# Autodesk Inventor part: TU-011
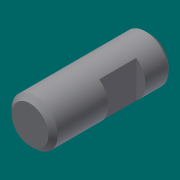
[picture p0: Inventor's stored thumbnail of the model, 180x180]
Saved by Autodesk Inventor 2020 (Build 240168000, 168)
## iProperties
Created: 2002-07
Part Number: TU-011
Document SubType Name: Modeling
Designer: PN
Description: Lock Pin
Density: 1 g/cm^3
Mass: 1.92325 g
Surface Area: 9.46666 cm^2
Volume: 1.92325 cm^3
Material: Generic
Appearance: Default
Control State: 0
Master: False
Checked Out: False
Shininess: 64.0
Angle Display Precision: 2
Document Length Units: 11269
Document Angle Units: 11279
Document Time Units: 11290
Document Mass Units: 11283
Document Length Units Precision: 3
Document Angle Units Precision: 2
Compacted: True
Density: 0.0
Volumn: 0.0
Area: 0.0
PropertySet Name: Model Information
Author: PN
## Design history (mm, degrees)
sketch "Sketch1"
  geometry: C1 r 5 at (0, 0); 1 further point
  constraints: 1 centre point, 1 coincident
  dimensions: "d0" = 10 diameter of C1
extrude "Extrusion1" new body sketch "Sketch1" stored distance "d1" = 26; taper "d2" = 0 deg
chamfer "Chamfer1" distance "d3" = 1; stored, may be unused: second distance "d4" = 1, angle "d10" = 45 deg
sketch "Sketch2"
  geometry: L1 (-5, -12)-(-5, 12) reference; L2 (-5, 7)-(-3, 7); L3 (-3, 7)-(-3, -1); L4 (-3, -1)-(-5, -1); L5 (-5, -1)-(-5, 7); L6 (-4, 13)-(4, 13) reference
  constraints: 8 end point, 2 parallel, 1 horizontal, 1 perpendicular, 1 point on line
  dimensions: "d5" = 2 distance of L2.start L2.end; "d6" = 8 distance of L2.end L3.end; "d7" = 6 distance between parallel lines of L2 L6
extrude "Extrusion2" cut sketch "Sketch2" extent not by distance; stored distance "d8" = 26; taper "d9" = 0 deg
workplane "Work Plane1"
body "Solid1"
